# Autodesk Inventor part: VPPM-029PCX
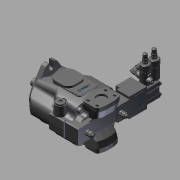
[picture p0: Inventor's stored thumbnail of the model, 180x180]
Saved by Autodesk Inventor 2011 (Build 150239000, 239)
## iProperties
Created: 2015-08
Part Number: VPPM-029PCX
Document SubType Name: Modeling
Designer: Храмов
Density: 1 g/cm^3
Author: Храмов
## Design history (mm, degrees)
derived "VPPM-029PCX-R55S_10N000_front.iam"
node "Твердое тело1"
node "48415101-R.ipt:1"
node "23370030.ipt:1"
sketch "42136800.ipt:1"
sketch "42136750.ipt:1"
sketch "42136800.ipt:2"
sketch "42136750.ipt:2"
sketch "0125156-00.ipt:1"
sketch "06870010.ipt:1"
sketch "06870000.ipt:1"
sketch "0530055.ipt:1"
sketch "0530055.ipt:2"
sketch "0530055.ipt:3"
sketch "0530055.ipt:4"
sketch "0551527.ipt:1"
sketch "0570181.ipt:1"
sketch "0770325.ipt:1"
sketch "0530528_.ipt:1"
sketch "0770325.ipt:2"
sketch "36740210.ipt:1"
sketch "0551527.ipt:2"
sketch "0570181.ipt:2"
sketch "0770325.ipt:3"
sketch "0530528_.ipt:2"
sketch "0770325.ipt:4"
sketch "36740210.ipt:2"
sketch "0771774.ipt:1"
sketch "0510169.ipt:1"
sketch "0551527.ipt:3"
sketch "0570181.ipt:3"
sketch "0550671.ipt:1"
sketch "0570182.ipt:1"
sketch "0771774.ipt:2"
sketch "3001110000.ipt:1"
sketch "0530521.ipt:1"
sketch "0530521.ipt:2"
sketch "0530080.ipt:1"
sketch "0530080.ipt:2"
sketch "0530080.ipt:3"
sketch "0530080.ipt:4"
node "47553520.ipt:1"
sketch "42760100.ipt:1"
node "39735000.ipt:1"
node "40690000.ipt:1"
sketch "0571495_.ipt:1"
sketch "3001200200-00.ipt:1"
